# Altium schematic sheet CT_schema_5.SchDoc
size 309 x 315 mm
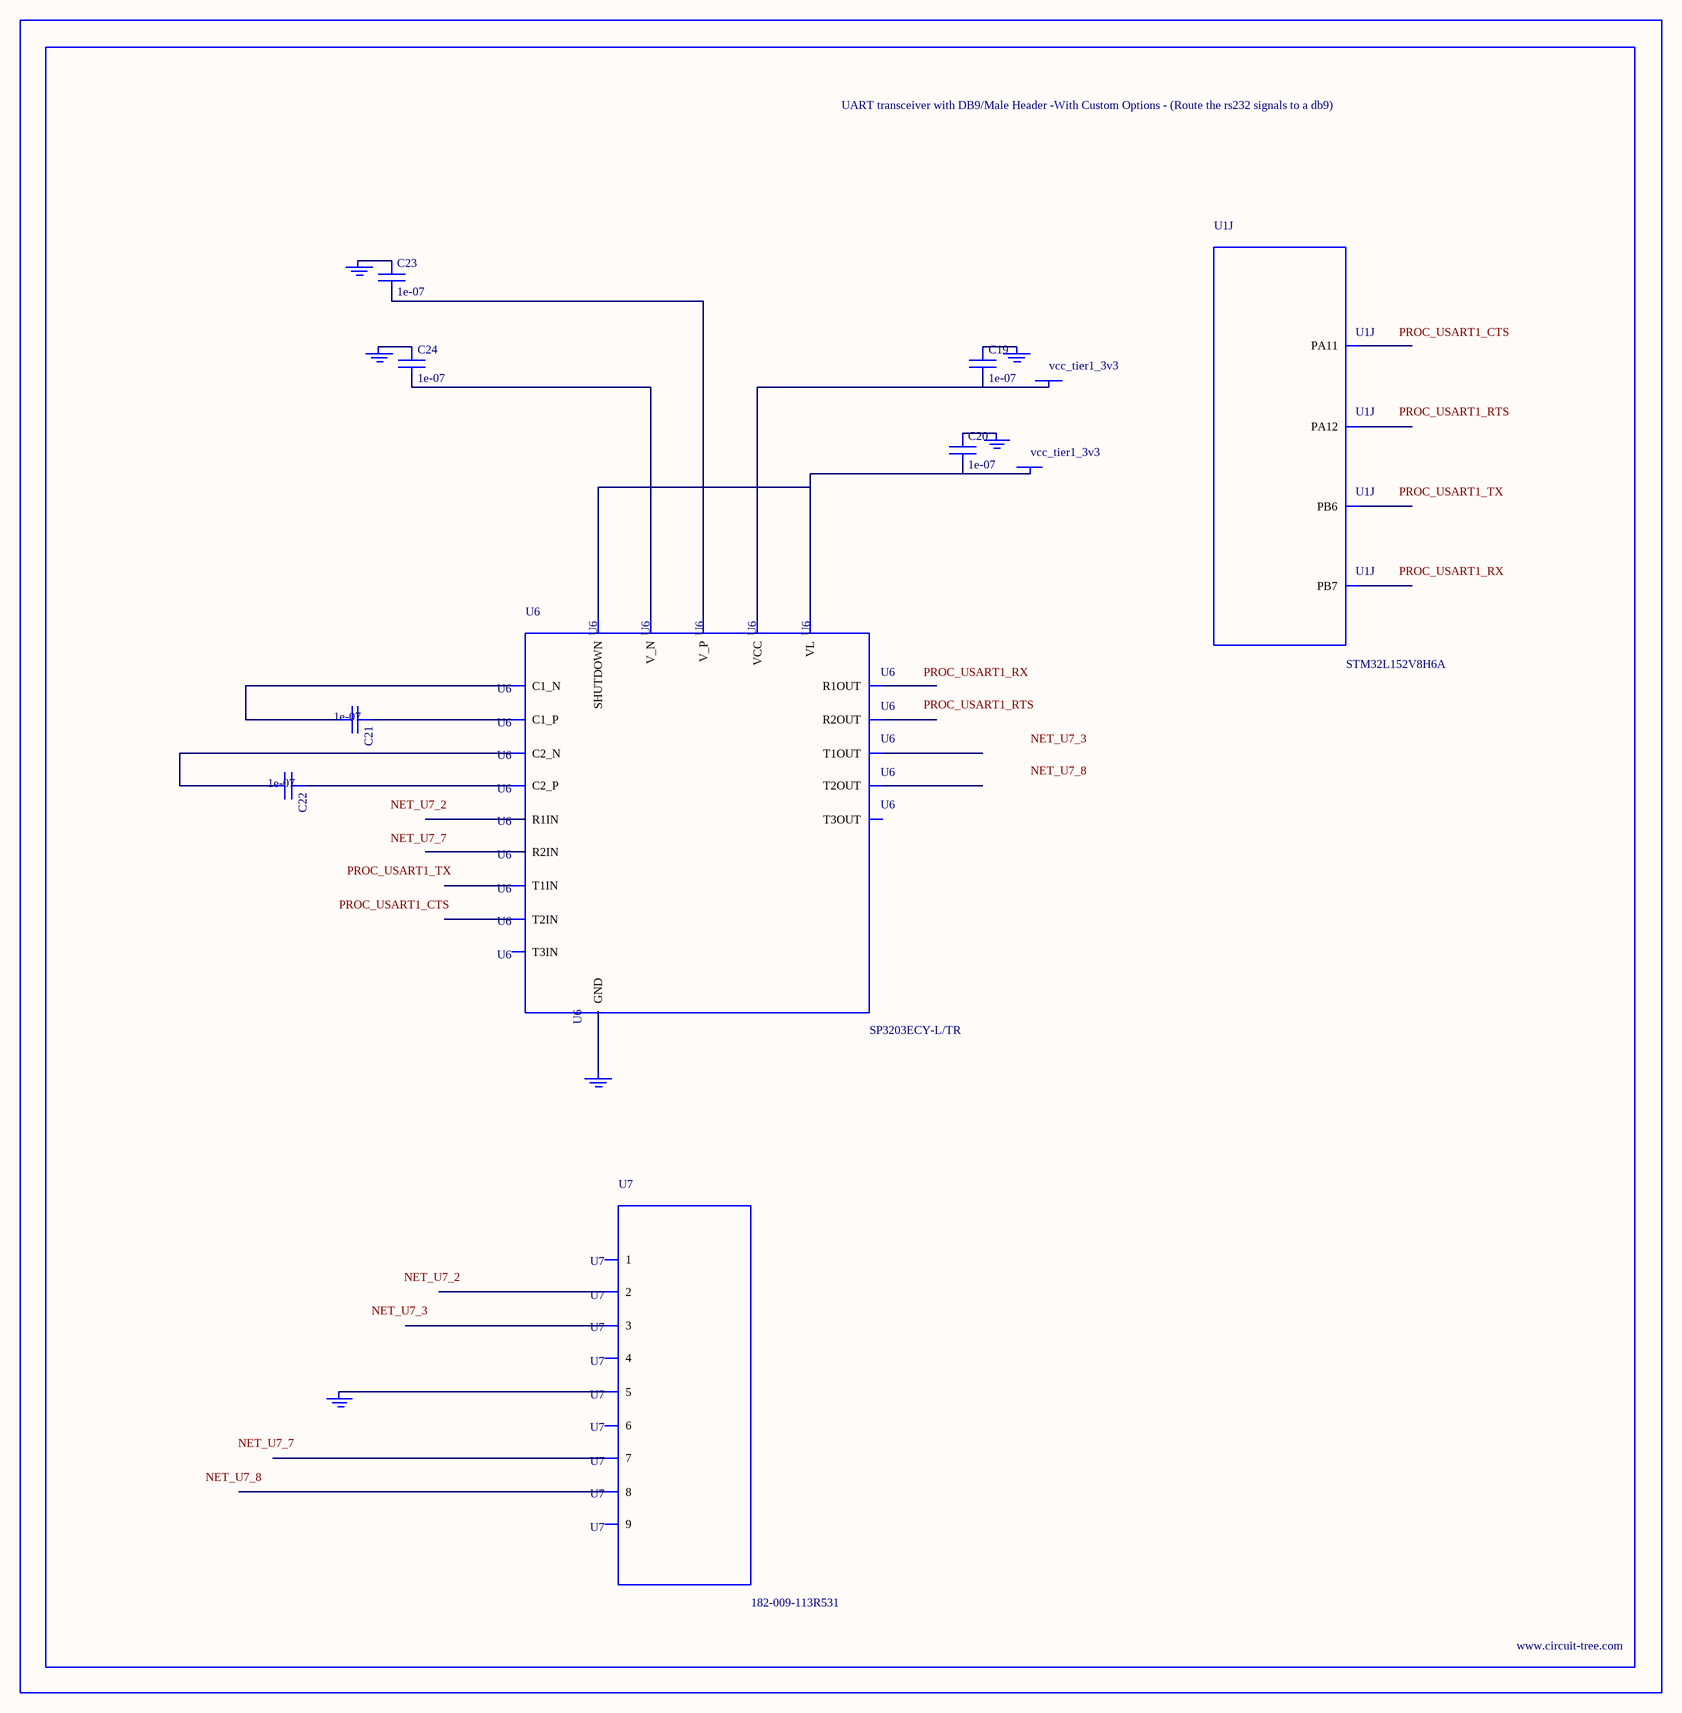
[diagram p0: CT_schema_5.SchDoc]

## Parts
BORDER4  (no value)
C19  1e-07  [C0402]
C20  1e-07  [C0402]
C21  1e-07  [C0402]
C22  1e-07  [C0402]
C23  1e-07  [C0402]
C24  1e-07  [C0402]
GND_INSTANCE_4_0  (no value)
GND_INSTANCE_4_1  (no value)
GND_INSTANCE_4_2  (no value)
GND_INSTANCE_4_3  (no value)
GND_INSTANCE_4_4  (no value)
GND_INSTANCE_4_5  (no value)
POWER_INSTANCE_4_0  vcc_tier1_3v3
POWER_INSTANCE_4_1  vcc_tier1_3v3
U1  STM32L152V8H6A  [UFBGA100]  (part J of 10)
U6  SP3203ECY-L/TR  [TSSOP20-I]
U7  182-009-113R531  [182-009-MALE]

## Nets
NetC19_1: C19.1 GND_INSTANCE_4_3.0(GND)
NetC19_2: C19.2 POWER_INSTANCE_4_1.0(PWR) U6.19(VCC)
NetC20_1: C20.1 GND_INSTANCE_4_2.0(GND)
NetC20_2: C20.2 POWER_INSTANCE_4_0.0(PWR) U6.12(VL) U6.20(SHUTDOWN)
NetC21_1: C21.1 U6.1(C1_P)
NetC21_2: C21.2 U6.3(C1_N)
NetC22_1: C22.1 U6.4(C2_P)
NetC22_2: C22.2 U6.5(C2_N)
NetC23_1: C23.1 GND_INSTANCE_4_0.0(GND)
NetC23_2: C23.2 U6.2(V_P)
NetC24_1: C24.1 GND_INSTANCE_4_1.0(GND)
NetC24_2: C24.2 U6.6(V_N)
NetGND_INSTANCE_4_4_0: GND_INSTANCE_4_4.0(GND) U6.18(GND)
NetGND_INSTANCE_4_5_0: GND_INSTANCE_4_5.0(GND) U7.5

Not connected (* = marked no-connect by the designer): U1 A12(PA12) B4(PB7) B5(PB6) B12(PA11); U6 7(T1IN) 8(T2IN) 9(T3IN) 10(R2OUT) 11(R1OUT) 13(R2IN) 14(R1IN) 15(T3OUT) 16(T2OUT) 17(T1OUT); U7 1 2 3 4 6 7 8 9

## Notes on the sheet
- Labels drawn without touching a wire or pin: NET_U7_2, NET_U7_3, NET_U7_7, NET_U7_8, PROC_USART1_CTS, PROC_USART1_RTS, PROC_USART1_RX, PROC_USART1_TX

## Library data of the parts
BORDER4 = BORDER_PAGE4
C19-C24 = C0402C104K3RACTU
GND_INSTANCE_4_0-GND_INSTANCE_4_5 = GND
POWER_INSTANCE_4_0 POWER_INSTANCE_4_1 = PWR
